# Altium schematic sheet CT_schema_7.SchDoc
size 224 x 213 mm
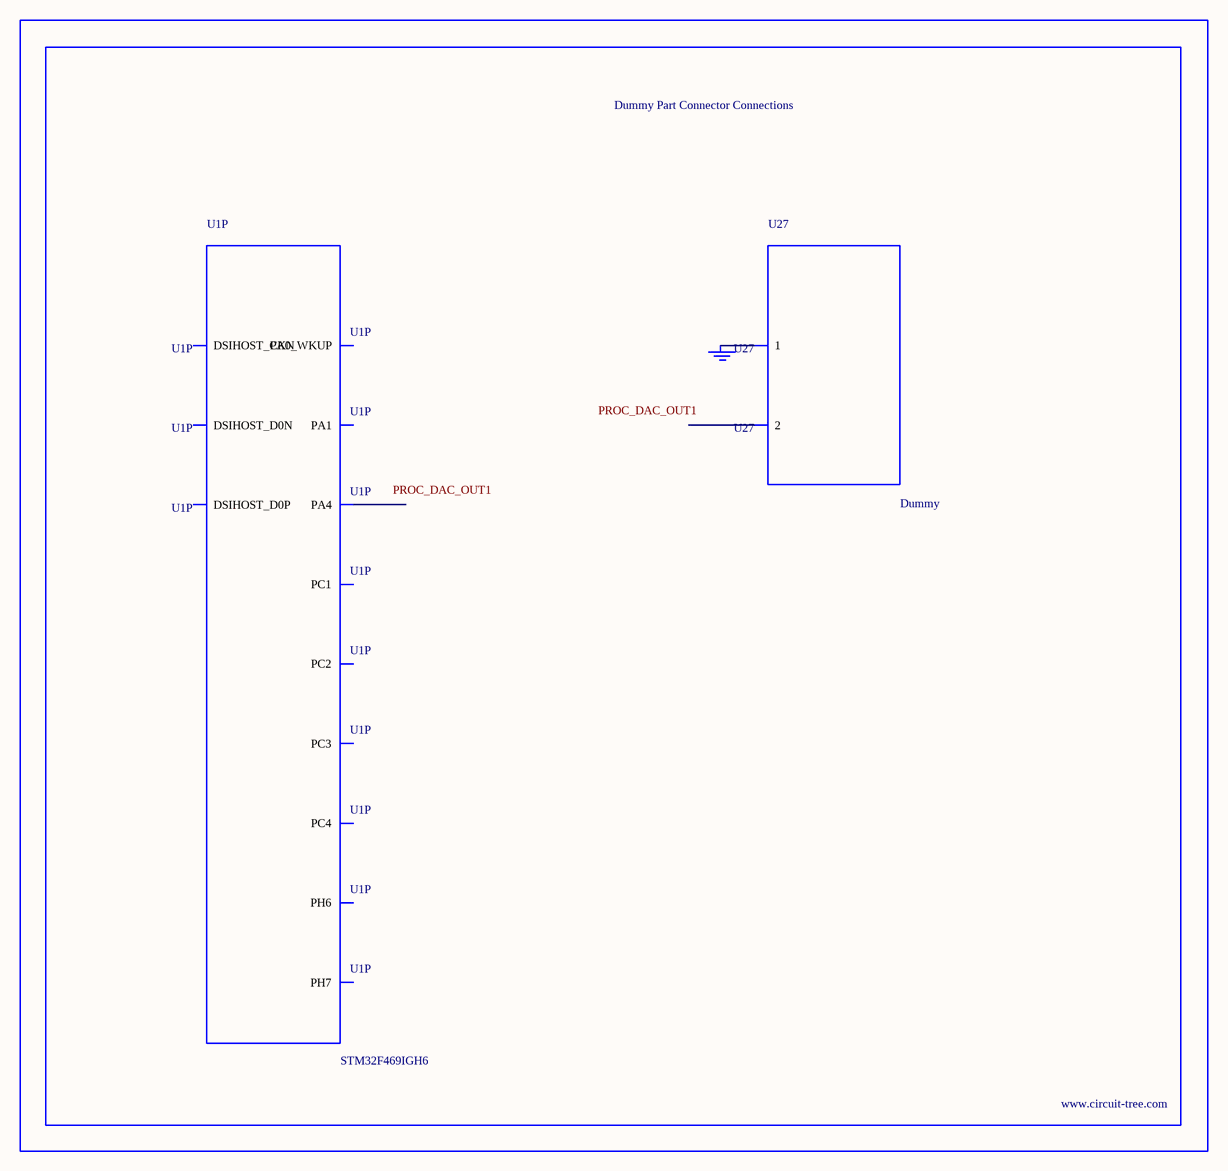
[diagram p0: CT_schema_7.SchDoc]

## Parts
BORDER6  (no value)
GND_INSTANCE_6_0  (no value)
U1  STM32F469IGH6  [UFBGA176]  (part P of 16)
U27  Dummy  [DUMMY_PACKAGE_324]

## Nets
NetGND_INSTANCE_6_0_0: GND_INSTANCE_6_0.0(GND) U27.1

Not connected (* = marked no-connect by the designer): U1 L13(DSIHOST_CKN) M3(PC1) M4(PC2) M5(PC3) M11(PH6) M12(DSIHOST_D0P) M13(DSIHOST_D0N) N2(PA1) N3(PA0_WKUP) N4(PA4) N5(PC4) N12(PH7); U27 2

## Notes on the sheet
- Labels drawn without touching a wire or pin: PROC_DAC_OUT1

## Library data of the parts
BORDER6 = BORDER_PAGE6
GND_INSTANCE_6_0 = GND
